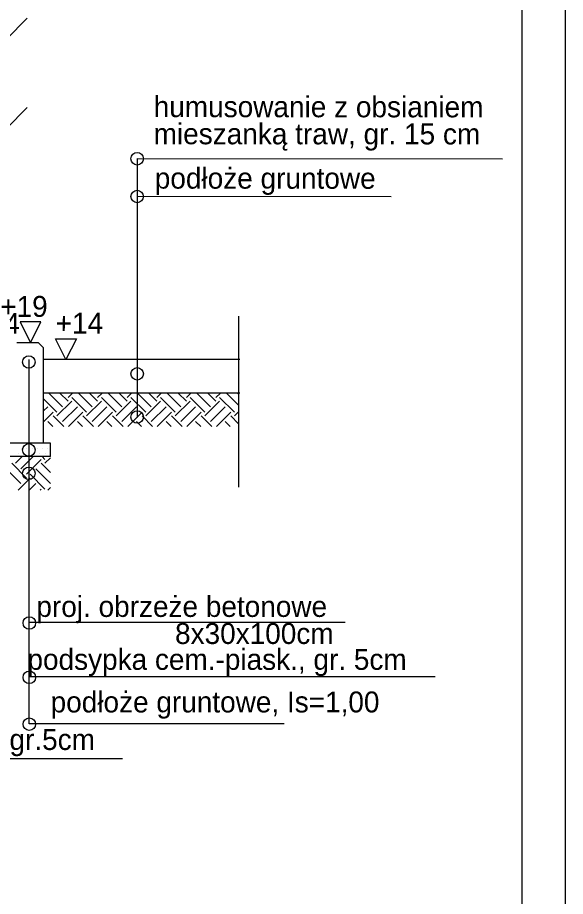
# Model space of a CAD drawing. Extents: x -219625893 to 7498339, y 5791790 to 5792761.
# Drawn here: x 7495494.5 to 7495527.2, y 5791843.4 to 5791896 of the extents above; entities that cross this region are included whole.
import ezdxf

# ---------------------------------------------------------------- set-up
doc = ezdxf.new("R2010")
doc.units = 0
for name, color, linetype in [('D_kons_wyp_grunt', 7, 'Continuous'), ('D_kons_wyp_podsypka_cem-piask', 7, 'Continuous'), ('D_wymiary_500', 7, 'Continuous'), ('Level 1', 7, 'Continuous'), ('Level 10', 7, 'Continuous'), ('wymiary', 7, 'Continuous')]:
    doc.layers.add(name, color=color, linetype=linetype)

msp = doc.modelspace()

# ---------------------------------------------------------------- linework, layer by layer
at = {"layer": 'D_kons_wyp_grunt'}
for p, q in [((7495507.711, 5791878.123), (7495507.711, 5791867.893)), ((7495496.859, 5791872.378), (7495496.058, 5791873.179)), ((7495497.191, 5791872.709), (7495496.376, 5791873.525)), ((7495497.522, 5791873.041), (7495497.038, 5791873.525)), ((7495497.522, 5791873.262), (7495497.785, 5791873.525)), ((7495498.627, 5791872.378), (7495497.743, 5791873.262)), ((7495498.958, 5791872.709), (7495498.143, 5791873.525)), ((7495499.29, 5791873.041), (7495498.806, 5791873.525)), ((7495499.29, 5791873.262), (7495499.553, 5791873.525)), ((7495500.395, 5791872.378), (7495499.511, 5791873.262)), ((7495500.726, 5791872.709), (7495499.911, 5791873.525)), ((7495501.058, 5791873.041), (7495500.574, 5791873.525)), ((7495501.058, 5791873.262), (7495501.32, 5791873.525)), ((7495502.163, 5791872.378), (7495501.279, 5791873.262)), ((7495502.494, 5791872.709), (7495501.679, 5791873.525)), ((7495502.825, 5791873.041), (7495502.342, 5791873.525)), ((7495502.825, 5791873.262), (7495503.088, 5791873.525)), ((7495503.93, 5791872.378), (7495503.046, 5791873.262)), ((7495504.262, 5791872.709), (7495503.447, 5791873.525)), ((7495504.593, 5791873.041), (7495504.11, 5791873.525)), ((7495504.593, 5791873.262), (7495504.856, 5791873.525)), ((7495505.698, 5791872.378), (7495504.814, 5791873.262)), ((7495506.03, 5791872.709), (7495505.214, 5791873.525)), ((7495506.361, 5791873.041), (7495505.877, 5791873.525)), ((7495506.361, 5791873.262), (7495506.624, 5791873.525)), ((7495507.466, 5791872.378), (7495506.582, 5791873.262)), ((7495507.711, 5791872.796), (7495506.982, 5791873.525)), ((7495507.711, 5791873.458), (7495507.645, 5791873.525)), ((7495496.058, 5791872.461), (7495496.307, 5791872.709)), ((7495496.859, 5791872.157), (7495497.743, 5791873.041)), ((7495497.191, 5791871.826), (7495498.075, 5791872.709)), ((7495498.627, 5791872.157), (7495499.511, 5791873.041)), ((7495498.958, 5791871.826), (7495499.842, 5791872.709)), ((7495500.395, 5791872.157), (7495501.279, 5791873.041)), ((7495500.726, 5791871.826), (7495501.61, 5791872.709)), ((7495502.163, 5791872.157), (7495503.046, 5791873.041)), ((7495502.494, 5791871.826), (7495503.378, 5791872.709)), ((7495503.93, 5791872.157), (7495504.814, 5791873.041)), ((7495504.262, 5791871.826), (7495505.146, 5791872.709)), ((7495505.698, 5791872.157), (7495506.582, 5791873.041)), ((7495506.03, 5791871.826), (7495506.913, 5791872.709)), ((7495496.058, 5791871.798), (7495496.638, 5791872.378)), ((7495497.271, 5791871.525), (7495496.638, 5791872.157)), ((7495497.553, 5791871.525), (7495498.406, 5791872.378)), ((7495499.038, 5791871.525), (7495498.406, 5791872.157)), ((7495499.32, 5791871.525), (7495500.174, 5791872.378)), ((7495500.806, 5791871.525), (7495500.174, 5791872.157)), ((7495501.088, 5791871.525), (7495501.942, 5791872.378)), ((7495502.574, 5791871.525), (7495501.942, 5791872.157)), ((7495502.856, 5791871.525), (7495503.709, 5791872.378)), ((7495504.342, 5791871.525), (7495503.709, 5791872.157)), ((7495504.624, 5791871.525), (7495505.477, 5791872.378)), ((7495506.11, 5791871.525), (7495505.477, 5791872.157)), ((7495506.392, 5791871.525), (7495507.245, 5791872.378)), ((7495507.711, 5791871.691), (7495507.245, 5791872.157)), ((7495507.466, 5791872.157), (7495507.711, 5791872.402)), ((7495496.608, 5791871.525), (7495496.307, 5791871.826)), ((7495498.376, 5791871.525), (7495498.075, 5791871.826)), ((7495500.143, 5791871.525), (7495499.842, 5791871.826)), ((7495501.911, 5791871.525), (7495501.61, 5791871.826)), ((7495503.679, 5791871.525), (7495503.378, 5791871.826)), ((7495505.447, 5791871.525), (7495505.146, 5791871.826)), ((7495507.214, 5791871.525), (7495506.913, 5791871.826))]:
    msp.add_line(p, q, dxfattribs=at)
at = {"layer": 'D_kons_wyp_podsypka_cem-piask'}
for p, q in [((7495494.744, 5791870.227), (7495494.744, 5791870.227)), ((7495495.057, 5791870.227), (7495495.057, 5791870.227)), ((7495495.369, 5791870.227), (7495495.369, 5791870.227)), ((7495495.682, 5791870.227), (7495495.682, 5791870.227)), ((7495495.994, 5791870.227), (7495495.994, 5791870.227)), ((7495496.307, 5791870.227), (7495496.307, 5791870.227)), ((7495494.588, 5791869.915), (7495494.588, 5791869.915)), ((7495494.9, 5791869.915), (7495494.9, 5791869.915)), ((7495495.213, 5791869.915), (7495495.213, 5791869.915)), ((7495495.525, 5791869.915), (7495495.525, 5791869.915)), ((7495495.838, 5791869.915), (7495495.838, 5791869.915)), ((7495496.15, 5791869.915), (7495496.15, 5791869.915)), ((7495496.463, 5791869.915), (7495496.463, 5791869.915))]:
    msp.add_line(p, q, dxfattribs=at)
at = {"layer": 'D_wymiary_500'}
for p, q in [((7495495.083, 5791895.925), (7495493.833, 5791894.675)), ((7495495.083, 5791890.592), (7495493.833, 5791889.342)), ((7495507.79, 5791873.525), (7495496.058, 5791873.525))]:
    msp.add_line(p, q, dxfattribs=at)
for centre in [(7495495.178, 5791875.38), (7495495.178, 5791870.128), (7495495.178, 5791868.729)]:
    msp.add_circle(centre, 0.375, dxfattribs=at)
at = {"layer": 'Level 1'}
for p, q in [((7495495.902, 5791877.775), (7495494.652, 5791877.774)), ((7495494.652, 5791877.774), (7495495.278, 5791876.525)), ((7495495.278, 5791876.525), (7495495.902, 5791877.775)), ((7495497.397, 5791875.525), (7495496.773, 5791876.775)), ((7495496.773, 5791876.775), (7495498.023, 5791876.774)), ((7495498.023, 5791876.774), (7495497.397, 5791875.525))]:
    msp.add_line(p, q, dxfattribs=at)
at = {"layer": 'Level 10'}
for p, q in [((7495527.248, 5791789.955), (7495527.248, 5791938.455)), ((7495524.648, 5791935.855), (7495524.648, 5791792.555)), ((7495495.758, 5791876.525), (7495494.458, 5791876.525)), ((7495495.758, 5791876.525), (7495496.058, 5791876.225)), ((7495496.058, 5791870.525), (7495496.058, 5791876.225)), ((7495507.79, 5791875.525), (7495496.058, 5791875.525)), ((7495496.468, 5791870.525), (7495494.048, 5791870.525)), ((7495496.468, 5791869.725), (7495496.468, 5791870.525)), ((7495496.468, 5791869.725), (7495494.048, 5791869.725))]:
    msp.add_line(p, q, dxfattribs=at)
at = {"layer": 'wymiary'}
for p, q in [((7495501.652, 5791887.54), (7495523.487, 5791887.524)), ((7495501.652, 5791887.54), (7495501.652, 5791872.064)), ((7495501.652, 5791885.285), (7495516.825, 5791885.274)), ((7495495.178, 5791875.53), (7495495.184, 5791853.757)), ((7495494.374, 5791869.331), (7495494.768, 5791869.725)), ((7495494.706, 5791869), (7495495.431, 5791869.725)), ((7495495.037, 5791868.668), (7495495.921, 5791869.552)), ((7495496.142, 5791869.552), (7495495.969, 5791869.725)), ((7495496.142, 5791869.331), (7495496.468, 5791869.658)), ((7495495.037, 5791868.447), (7495494.153, 5791869.331)), ((7495496.468, 5791868.121), (7495495.59, 5791869)), ((7495496.468, 5791868.784), (7495495.921, 5791869.331)), ((7495494.706, 5791868.116), (7495494.048, 5791868.774)), ((7495494.535, 5791867.725), (7495495.258, 5791868.447)), ((7495496.142, 5791867.784), (7495495.258, 5791868.668)), ((7495495.198, 5791867.725), (7495495.59, 5791868.116)), ((7495496.303, 5791867.725), (7495496.468, 5791867.89)), ((7495495.861, 5791867.725), (7495495.921, 5791867.784)), ((7495514.089, 5791859.821), (7495495.197, 5791859.807)), ((7495519.456, 5791856.575), (7495495.197, 5791856.557)), ((7495510.43, 5791853.768), (7495495.197, 5791853.757)), ((7495500.769, 5791851.674), (7495465.933, 5791851.648))]:
    msp.add_line(p, q, dxfattribs=at)
for centre in [(7495501.652, 5791887.527), (7495501.652, 5791885.271), (7495501.652, 5791874.674), (7495501.652, 5791872.091), (7495495.205, 5791859.786), (7495495.205, 5791856.536), (7495495.205, 5791853.736)]:
    msp.add_circle(centre, 0.375, dxfattribs=at)

# ---------------------------------------------------------------- texts
at = {"layer": 'Level 10'}
for s, p in [('proj. obrzeże betonowe ', (7495495.628, 5791860.147)), ('8x30x100cm ', (7495503.915, 5791858.53)), ('podsypka cem.-piask., gr. 5cm ', (7495495.093, 5791856.984)), ('podłoże gruntowe, Is=1,00', (7495496.479, 5791854.44))]:
    msp.add_text(s, height=1.25, dxfattribs=at).set_placement(p)
at = {"layer": 'wymiary'}
for s, height, rotation, p in [('humusowanie z obsianiem ', 1.25089, 359.9571, (7495502.636, 5791890.014)), ('mieszanką traw, gr. 15 cm', 1.25089, 359.9571, (7495502.634, 5791888.395)), ('podłoże gruntowe ', 1.25089, 359.9571, (7495502.702, 5791885.742)), ('+19', 1.25, 0.0429, (7495493.468, 5791878.076)), ('+14', 1.25, 359.9571, (7495491.808, 5791877.068)), ('+14', 1.25, 359.9571, (7495496.78, 5791877.078)), ('podsypka cementowo-piaskowa 1:4, gr.5cm', 1.25089, 0.0429, (7495466.588, 5791852.173))]:
    msp.add_text(s, height=height, rotation=rotation, dxfattribs=at).set_placement(p)

doc.saveas('drawing.dxf')
